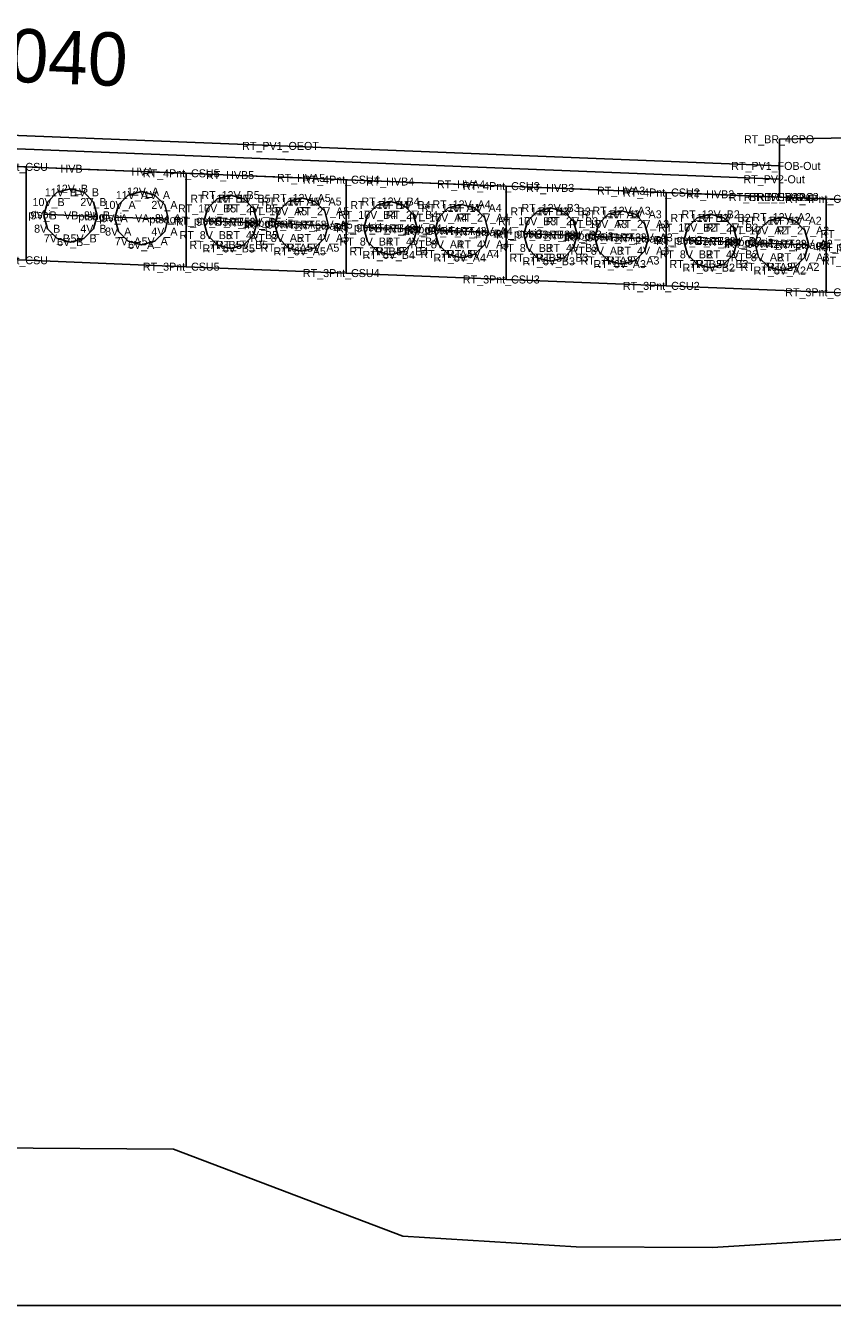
# Model space of a CAD drawing. Extents: x -26 to 1163, y -10 to 9537.
# Drawn here: x 84.24 to 99.37, y 6000 to 6023.98 of the extents above; entities that cross this region are included whole.
import ezdxf

# ---------------------------------------------------------------- set-up
doc = ezdxf.new("R2010")
doc.units = 0
for name, color, linetype in [('Exist Cross Section Cell', 7, 'Continuous'), ('Exist XS Ground Line', 7, 'Continuous'), ('Prop CMT Concrete Structures', 7, 'Continuous'), ('Prop CMT Corridor Surface Symbology Blue', 7, 'Continuous'), ('Prop CMT Pvmt Course 1', 7, 'Continuous'), ('Prop CMT Pvmt Course 2', 7, 'Continuous'), ('Prop XS SE Text', 7, 'Continuous'), ('Scratch_Level_0', 7, 'Continuous')]:
    doc.layers.add(name, color=color, linetype=linetype)

msp = doc.modelspace()

# ---------------------------------------------------------------- linework, layer by layer
at = {"layer": 'Exist Cross Section Cell'}
msp.add_line((80, 6000), (160, 6000), dxfattribs=at)
at = {"layer": 'Exist XS Ground Line'}
msp.add_lwpolyline([(54.51, 6004.315), (62.713, 6003.678), (73.379, 6003.022), (80, 6002.975), (87.016, 6002.925), (91.312, 6001.299), (94.565, 6001.099), (97.121, 6001.084), (109.199, 6001.839), (119.662, 6002.66), (122.228, 6004.967), (124.251, 6006.909), (129.58, 6007.46), (132.249, 6006.951), (132.875, 6007.018), (147.194, 6007.634), (148.841, 6007.735), (150.67, 6007.781), (160, 6007.577)], dxfattribs=at)
at = {"layer": 'Prop CMT Concrete Structures'}
for points in [[(98.375, 6020.772), (98.376, 6021.855), (103.875, 6021.965), (103.876, 6022.309), (105.166, 6022.309), (105.167, 6020.5)], [(81.25, 6021.457), (82.083, 6021.423), (83.417, 6021.37), (84.25, 6021.337)], [(84.25, 6021.337), (84.25, 6019.587)], [(84.25, 6021.337), (85.083, 6021.303), (86.417, 6021.25), (87.25, 6021.217)], [(84.25, 6019.587), (84.25, 6021.337)], [(87.25, 6021.217), (88.083, 6021.183), (89.417, 6021.13), (90.25, 6021.097)], [(87.25, 6019.467), (87.25, 6021.217)], [(87.25, 6021.217), (87.25, 6019.467)], [(90.25, 6021.097), (90.25, 6019.347)], [(90.25, 6021.097), (91.083, 6021.063), (92.417, 6021.01), (93.25, 6020.977)], [(90.25, 6019.347), (90.25, 6021.097)], [(93.25, 6020.977), (93.25, 6019.227)], [(93.25, 6020.977), (94.083, 6020.943), (95.417, 6020.89), (96.25, 6020.857)], [(93.25, 6019.227), (93.25, 6020.977)], [(84.583, 6020.428), (84.65, 6020.678), (84.833, 6020.861), (85.083, 6020.928)], [(85.083, 6020.928), (85.333, 6020.861), (85.516, 6020.678), (85.583, 6020.428)], [(85.917, 6020.375), (85.984, 6020.625), (86.167, 6020.808), (86.417, 6020.875)], [(86.417, 6020.875), (86.667, 6020.808), (86.85, 6020.625), (86.917, 6020.375)], [(87.583, 6020.308), (87.65, 6020.558), (87.833, 6020.741), (88.083, 6020.808)], [(88.083, 6020.808), (88.333, 6020.741), (88.516, 6020.558), (88.583, 6020.308)], [(88.917, 6020.255), (88.984, 6020.505), (89.167, 6020.688), (89.417, 6020.755)], [(89.417, 6020.755), (89.667, 6020.688), (89.85, 6020.505), (89.917, 6020.255)], [(96.25, 6020.857), (96.25, 6019.107)], [(96.25, 6020.857), (97.083, 6020.823), (98.417, 6020.77), (99.25, 6020.737)], [(96.25, 6019.107), (96.25, 6020.857)], [(105.167, 6020.5), (98.375, 6020.772)], [(99.25, 6020.737), (99.25, 6018.987)], [(99.25, 6020.737), (100.083, 6020.703), (101.417, 6020.65), (102.25, 6020.617)], [(99.25, 6018.987), (99.25, 6020.737)], [(90.583, 6020.188), (90.65, 6020.438), (90.833, 6020.621), (91.083, 6020.688)], [(91.083, 6020.688), (91.333, 6020.621), (91.516, 6020.438), (91.583, 6020.188)], [(91.917, 6020.135), (91.984, 6020.385), (92.167, 6020.568), (92.417, 6020.635)], [(92.417, 6020.635), (92.667, 6020.568), (92.85, 6020.385), (92.917, 6020.135)], [(93.583, 6020.068), (93.65, 6020.318), (93.833, 6020.501), (94.083, 6020.568)], [(94.083, 6020.568), (94.333, 6020.501), (94.516, 6020.318), (94.583, 6020.068)], [(94.917, 6020.015), (94.984, 6020.265), (95.167, 6020.448), (95.417, 6020.515)], [(95.417, 6020.515), (95.667, 6020.448), (95.85, 6020.265), (95.917, 6020.015)], [(85.583, 6020.428), (85.516, 6020.178), (85.333, 6019.995), (85.083, 6019.928), (84.833, 6019.995), (84.65, 6020.178), (84.583, 6020.428)], [(86.917, 6020.375), (86.85, 6020.125), (86.667, 6019.942), (86.417, 6019.875), (86.167, 6019.942), (85.984, 6020.125), (85.917, 6020.375)], [(88.583, 6020.308), (88.516, 6020.058), (88.333, 6019.875), (88.083, 6019.808), (87.833, 6019.875), (87.65, 6020.058), (87.583, 6020.308)], [(89.917, 6020.255), (89.85, 6020.005), (89.667, 6019.822), (89.417, 6019.755), (89.167, 6019.822), (88.984, 6020.005), (88.917, 6020.255)], [(96.583, 6019.948), (96.65, 6020.198), (96.833, 6020.381), (97.083, 6020.448)], [(97.083, 6020.448), (97.333, 6020.381), (97.516, 6020.198), (97.583, 6019.948)], [(97.917, 6019.895), (97.984, 6020.145), (98.167, 6020.328), (98.417, 6020.395)], [(98.417, 6020.395), (98.667, 6020.328), (98.85, 6020.145), (98.917, 6019.895)], [(91.583, 6020.188), (91.516, 6019.938), (91.333, 6019.755), (91.083, 6019.688), (90.833, 6019.755), (90.65, 6019.938), (90.583, 6020.188)], [(92.917, 6020.135), (92.85, 6019.885), (92.667, 6019.702), (92.417, 6019.635), (92.167, 6019.702), (91.984, 6019.885), (91.917, 6020.135)], [(94.583, 6020.068), (94.516, 6019.818), (94.333, 6019.635), (94.083, 6019.568), (93.833, 6019.635), (93.65, 6019.818), (93.583, 6020.068)], [(95.917, 6020.015), (95.85, 6019.765), (95.667, 6019.582), (95.417, 6019.515), (95.167, 6019.582), (94.984, 6019.765), (94.917, 6020.015)], [(97.583, 6019.948), (97.516, 6019.698), (97.333, 6019.515), (97.083, 6019.448), (96.833, 6019.515), (96.65, 6019.698), (96.583, 6019.948)], [(98.917, 6019.895), (98.85, 6019.645), (98.667, 6019.462), (98.417, 6019.395), (98.167, 6019.462), (97.984, 6019.645), (97.917, 6019.895)], [(84.25, 6019.587), (81.25, 6019.707)], [(87.25, 6019.467), (84.25, 6019.587)], [(90.25, 6019.347), (87.25, 6019.467)], [(93.25, 6019.227), (90.25, 6019.347)], [(96.25, 6019.107), (93.25, 6019.227)], [(99.25, 6018.987), (96.25, 6019.107)], [(102.25, 6018.867), (99.25, 6018.987)]]:
    msp.add_lwpolyline(points, dxfattribs=at)
at = {"layer": 'Prop CMT Corridor Surface Symbology Blue'}
for points in [[(84.593, 6020.448), (85.083, 6020.428), (85.573, 6020.409)], [(85.927, 6020.395), (86.417, 6020.375), (86.907, 6020.355)], [(87.593, 6020.328), (88.083, 6020.308), (88.573, 6020.289)], [(88.927, 6020.275), (89.417, 6020.255), (89.907, 6020.235)], [(90.593, 6020.208), (91.083, 6020.188), (91.573, 6020.169)], [(91.927, 6020.155), (92.417, 6020.135), (92.907, 6020.115)], [(93.593, 6020.088), (94.083, 6020.068), (94.573, 6020.049)], [(94.927, 6020.035), (95.417, 6020.015), (95.907, 6019.995)], [(96.593, 6019.968), (97.083, 6019.948), (97.573, 6019.929)], [(97.927, 6019.915), (98.417, 6019.895), (98.907, 6019.875)]]:
    msp.add_lwpolyline(points, dxfattribs=at)
at = {"layer": 'Prop CMT Pvmt Course 1'}
for points in [[(80, 6022.09), (89, 6021.73), (98.376, 6021.355)], [(98.376, 6021.355), (98.376, 6021.105), (80, 6021.84)]]:
    msp.add_lwpolyline(points, dxfattribs=at)
at = {"layer": 'Prop CMT Pvmt Course 2'}
for points in [[(80, 6021.84), (98.376, 6021.105)], [(98.376, 6021.105), (98.375, 6020.772), (80, 6021.507)]]:
    msp.add_lwpolyline(points, dxfattribs=at)

# ---------------------------------------------------------------- texts
at = {"layer": 'Prop XS SE Text'}
msp.add_text('0.040', height=1, rotation=357.7094, dxfattribs=at).set_placement((82.791, 6022.979))
at = {"layer": 'Scratch_Level_0'}
for s, p in [('RT_BR_4CPO', (97.71, 6021.78)), ('RT_PV1_OEOT', (88.302, 6021.655)), ('RT_PV1_FOB-Out', (97.471, 6021.28)), ('4Pnt_CSU', (83.714, 6021.262)), ('HVB', (84.897, 6021.228)), ('HVA', (86.228, 6021.175)), ('RT_4Pnt_CSU5', (86.441, 6021.142)), ('RT_HVB5', (87.624, 6021.108)), ('RT_HVA5', (88.955, 6021.055)), ('12V_B', (84.81, 6020.853)), ('12V_A', (86.141, 6020.8)), ('RT_4Pnt_CSU4', (89.441, 6021.022)), ('RT_HVB4', (90.624, 6020.988)), ('RT_HVA4', (91.955, 6020.935)), ('RT_4Pnt_CSU3', (92.441, 6020.902)), ('RT_HVB3', (93.624, 6020.868)), ('RT_HVA3', (94.955, 6020.815)), ('RT_PV2-Out', (97.701, 6021.03)), ('10V_B', (84.372, 6020.603)), ('11V_B', (84.603, 6020.786)), ('1V_B', (85.128, 6020.786)), ('2V_B', (85.268, 6020.603)), ('11V_A', (85.934, 6020.733)), ('1V_A', (86.459, 6020.733)), ('RT_11V_B5', (87.33, 6020.666)), ('RT_12V_B5', (87.538, 6020.733)), ('RT_1V_B5', (87.855, 6020.666)), ('RT_11V_A5', (88.661, 6020.613)), ('RT_12V_A5', (88.869, 6020.68)), ('RT_1V_A5', (89.186, 6020.613)), ('RT_12V_B4', (90.538, 6020.613)), ('RT_12V_A4', (91.869, 6020.56)), ('RT_4Pnt_CSU2', (95.441, 6020.782)), ('RT_HVB2', (96.624, 6020.748)), ('RT_BR_VCB-Out3', (97.427, 6020.697)), ('RT_BR_5CPO', (97.709, 6020.697)), ('RT_HVA2', (97.955, 6020.695)), ('RT_4Pnt_CSU1', (98.483, 6020.662)), ('ptsbi', (84.292, 6020.373)), ('9V_B', (84.335, 6020.353)), ('VB', (84.964, 6020.353)), ('ptsbo', (85.232, 6020.334)), ('3V_B', (85.335, 6020.353)), ('ptsai', (85.624, 6020.32)), ('10V_A', (85.703, 6020.55)), ('2V_A', (86.599, 6020.55)), ('RT_10V_B5', (87.099, 6020.483)), ('RT_2V_B5', (87.995, 6020.483)), ('RT_10V_A5', (88.43, 6020.43)), ('RT_2V_A5', (89.326, 6020.43)), ('RT_10V_B4', (90.099, 6020.363)), ('RT_11V_B4', (90.33, 6020.546)), ('RT_1V_B4', (90.855, 6020.546)), ('RT_2V_B4', (90.995, 6020.363)), ('RT_11V_A4', (91.661, 6020.493)), ('RT_1V_A4', (92.186, 6020.493)), ('RT_11V_B3', (93.33, 6020.426)), ('RT_12V_B3', (93.538, 6020.493)), ('RT_1V_B3', (93.855, 6020.426)), ('RT_11V_A3', (94.661, 6020.373)), ('RT_12V_A3', (94.869, 6020.44)), ('RT_1V_A3', (95.186, 6020.373)), ('RT_12V_B2', (96.538, 6020.373)), ('RT_12V_A2', (97.869, 6020.32)), ('8V_B', (84.402, 6020.103)), ('4V_B', (85.268, 6020.103)), ('9V_A', (85.666, 6020.3)), ('VA', (86.295, 6020.3)), ('ptsao', (86.564, 6020.28)), ('3V_A', (86.666, 6020.3)), ('RT_ptsbi5', (87.019, 6020.253)), ('RT_9V_B5', (87.062, 6020.233)), ('RT_VB5', (87.691, 6020.233)), ('RT_ptsbo5', (87.959, 6020.214)), ('RT_3V_B5', (88.062, 6020.233)), ('RT_ptsai5', (88.351, 6020.2)), ('RT_9V_A5', (88.393, 6020.18)), ('RT_VA5', (89.022, 6020.18)), ('RT_ptsao5', (89.291, 6020.16)), ('RT_3V_A5', (89.393, 6020.18)), ('RT_ptsbi4', (90.019, 6020.133)), ('RT_9V_B4', (90.062, 6020.113)), ('RT_VB4', (90.691, 6020.113)), ('RT_ptsbo4', (90.959, 6020.094)), ('RT_3V_B4', (91.062, 6020.113)), ('RT_ptsai4', (91.351, 6020.08)), ('RT_10V_A4', (91.43, 6020.31)), ('RT_2V_A4', (92.326, 6020.31)), ('RT_10V_B3', (93.099, 6020.243)), ('RT_2V_B3', (93.995, 6020.243)), ('RT_10V_A3', (94.43, 6020.19)), ('RT_2V_A3', (95.326, 6020.19)), ('RT_10V_B2', (96.099, 6020.123)), ('RT_11V_B2', (96.33, 6020.306)), ('RT_1V_B2', (96.855, 6020.306)), ('RT_2V_B2', (96.995, 6020.123)), ('RT_11V_A2', (97.661, 6020.253)), ('RT_1V_A2', (98.186, 6020.253)), ('7V_B', (84.585, 6019.92)), ('6V_B', (84.832, 6019.853)), ('5V_B', (85.085, 6019.92)), ('8V_A', (85.733, 6020.05)), ('7V_A', (85.916, 6019.867)), ('5V_A', (86.416, 6019.867)), ('4V_A', (86.599, 6020.05)), ('RT_8V_B5', (87.129, 6019.983)), ('RT_4V_B5', (87.995, 6019.983)), ('RT_8V_A5', (88.46, 6019.93)), ('RT_4V_A5', (89.326, 6019.93)), ('RT_8V_B4', (90.129, 6019.863)), ('RT_4V_B4', (90.995, 6019.863)), ('RT_9V_A4', (91.393, 6020.06)), ('RT_VA4', (92.022, 6020.06)), ('RT_ptsao4', (92.291, 6020.04)), ('RT_3V_A4', (92.393, 6020.06)), ('RT_ptsbi3', (93.019, 6020.013)), ('RT_9V_B3', (93.062, 6019.993)), ('RT_VB3', (93.691, 6019.993)), ('RT_ptsbo3', (93.959, 6019.974)), ('RT_3V_B3', (94.062, 6019.993)), ('RT_ptsai3', (94.351, 6019.96)), ('RT_9V_A3', (94.393, 6019.94)), ('RT_VA3', (95.022, 6019.94)), ('RT_ptsao3', (95.291, 6019.92)), ('RT_3V_A3', (95.393, 6019.94)), ('RT_ptsbi2', (96.019, 6019.893)), ('RT_9V_B2', (96.062, 6019.873)), ('RT_VB2', (96.691, 6019.873)), ('RT_ptsbo2', (96.959, 6019.854)), ('RT_3V_B2', (97.062, 6019.873)), ('RT_ptsai2', (97.351, 6019.84)), ('RT_10V_A2', (97.43, 6020.07)), ('RT_2V_A2', (98.326, 6020.07)), ('RT_10V_B1', (99.141, 6020.003)), ('6V_A', (86.163, 6019.8)), ('RT_7V_B5', (87.312, 6019.8)), ('RT_6V_B5', (87.559, 6019.733)), ('RT_5V_B5', (87.812, 6019.8)), ('RT_7V_A5', (88.643, 6019.747)), ('RT_6V_A5', (88.89, 6019.68)), ('RT_5V_A5', (89.143, 6019.747)), ('RT_7V_B4', (90.312, 6019.68)), ('RT_6V_B4', (90.559, 6019.613)), ('RT_5V_B4', (90.812, 6019.68)), ('RT_8V_A4', (91.46, 6019.81)), ('RT_7V_A4', (91.643, 6019.627)), ('RT_5V_A4', (92.143, 6019.627)), ('RT_4V_A4', (92.326, 6019.81)), ('RT_8V_B3', (93.129, 6019.743)), ('RT_4V_B3', (93.995, 6019.743)), ('RT_8V_A3', (94.46, 6019.69)), ('RT_4V_A3', (95.326, 6019.69)), ('RT_8V_B2', (96.129, 6019.623)), ('RT_4V_B2', (96.995, 6019.623)), ('RT_9V_A2', (97.393, 6019.82)), ('RT_VA2', (98.022, 6019.82)), ('RT_ptsao2', (98.291, 6019.8)), ('RT_3V_A2', (98.393, 6019.82)), ('RT_ptsbi1', (99.062, 6019.773)), ('RT_9V_B1', (99.105, 6019.753)), ('3Pnt_CSU', (83.714, 6019.512)), ('RT_3Pnt_CSU5', (86.441, 6019.392)), ('RT_6V_A4', (91.89, 6019.56)), ('RT_7V_B3', (93.312, 6019.56)), ('RT_6V_B3', (93.559, 6019.493)), ('RT_5V_B3', (93.812, 6019.56)), ('RT_7V_A3', (94.643, 6019.507)), ('RT_6V_A3', (94.89, 6019.44)), ('RT_5V_A3', (95.143, 6019.507)), ('RT_7V_B2', (96.312, 6019.44)), ('RT_6V_B2', (96.559, 6019.373)), ('RT_5V_B2', (96.812, 6019.44)), ('RT_8V_A2', (97.46, 6019.57)), ('RT_7V_A2', (97.643, 6019.387)), ('RT_5V_A2', (98.143, 6019.387)), ('RT_4V_A2', (98.326, 6019.57)), ('RT_8V_B1', (99.172, 6019.503)), ('RT_3Pnt_CSU4', (89.441, 6019.272)), ('RT_3Pnt_CSU3', (92.441, 6019.152)), ('RT_6V_A2', (97.89, 6019.32)), ('RT_3Pnt_CSU2', (95.441, 6019.032)), ('RT_3Pnt_CSU1', (98.483, 6018.912))]:
    msp.add_text(s, height=0.15, dxfattribs=at).set_placement(p)

doc.saveas('drawing.dxf')
